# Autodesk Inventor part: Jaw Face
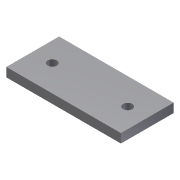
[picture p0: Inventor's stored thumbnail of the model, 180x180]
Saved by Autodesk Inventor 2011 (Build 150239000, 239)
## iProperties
Shininess: 77.0
Length Units: 11269
Angle Units: 11279
Time Units: 11290
Mass Units: 11283
Length Display Precision: 3
Angle Display Precision: 2
Compacted: True
Created: 2002-02
Part Number: Jaw Face
Document SubType Name: Modeling
Designer: ***
Density: 1 g/cm^3
Mass: 15.6207 g
Surface Area: 67.651 cm^2
Volume: 15.6207 cm^3
Density: 0.0
Volumn: 0.0
Area: 0.0
PropertySet Name: Model Information
Control State: 0
Master: False
Checked Out: False
Author: ***
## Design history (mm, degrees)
sketch "Sketch1"
  geometry: L1 (-79.661, -8.43)-(-3.661, -8.43); L2 (-3.661, -8.43)-(-3.661, -43.43); L3 (-3.661, -43.43)-(-79.661, -43.43); L4 (-79.661, -43.43)-(-79.661, -8.43); C1 r 3 at (-66.661, -25.93); C2 r 3 at (-16.661, -25.93)
  constraints: 8 end point, 2 centre point, 2 parallel, 1 equal radius, 1 horizontal, 1 perpendicular
  dimensions: "d0" = 76 distance of L2.end L3.end; "d1" = 6 diameter of C1; "d2" = 50 distance of C2.centre C1.centre; "d3" = 35 distance of L1.end L2.end; "d4" = 17.5 distance from line of L3 C2.centre; "d5" = 13 distance from line of L2 C2.centre; "d6" = 13 distance from line of L4 C1.centre
extrude "Extrusion1" new body sketch "Sketch1" stored distance "d7" = 6; taper "d8" = 0 deg
body "Solid1"
